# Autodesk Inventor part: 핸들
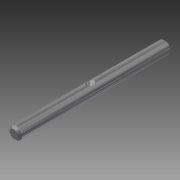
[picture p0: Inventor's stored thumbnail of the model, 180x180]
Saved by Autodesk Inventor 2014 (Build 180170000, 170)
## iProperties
Created: 2019-04
Part Number: 핸들
Material: 스테인리스강
Document SubType Name: Modeling
Designer: mduedu
Density: 1 g/cm^3
Appearance: 반광택
Author: mduedu
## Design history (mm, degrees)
sketch "스케치1"
  geometry: C1 r 3 at (0, 0); 1 further point
  constraints: 1 centre point, 1 coincident
  dimensions: "d0" = 6 diameter of C1
extrude "돌출1" new body sketch "스케치1" stored distance "d1" = 74; taper "d2" = 0 deg
chamfer "모따기1" distance "d3" = 1; stored, may be unused: second distance "d4" = 2, angle "d5" = 45 deg
sketch "스케치2"
  geometry: L1 (-36, 3)-(36, 3) reference; L2 (0, 3)-(0, 1); L3 (0, 1)-(2, 3); L4 (0, 3)-(2, 3); 1 further point
  constraints: 6 end point, 2 perpendicular, 1 midpoint, 1 point on line
  dimensions: "d6" = 4 diameter of L3.end L2; "d8" = 45 deg angle of L3 L2
revolve "회전1" sketch "스케치2" stored, may be unused: angle "d10" = 90 deg
node "작업점1"
  node "작업축1"
  node "작업 평면1"
sketch "Sketch3"
  geometry: L1 (36, 3)-(37, 2) reference; L2 (37, 2)-(37, -2) reference; L3 (37, -2)-(36, -3) reference; L4 (36, -3)-(-36, -3) reference; L5 (-36, -3)-(-37, -2) reference; L6 (-37, -2)-(-37, 2) reference; L7 (-37, 2)-(-36, 3) reference; L8 (-36, 3)-(-2, 3) reference; L9 (-2, 3)-(0, 1) reference; L10 (0, 1)-(2, 3) reference; L11 (2, 3)-(36, 3) reference; 1 further point
  node "Project Cut Edges1"
node "솔리드1"
